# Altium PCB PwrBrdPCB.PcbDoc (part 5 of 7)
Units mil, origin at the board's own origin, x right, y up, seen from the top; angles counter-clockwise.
Board outline 8000 x 5500 mil, 4 copper layers (Top Layer, Internal 1, Internal 2, Bottom Layer), stack 61.834 mil thick; 682 components, 380 nets, 1899 pads, 766 vias.
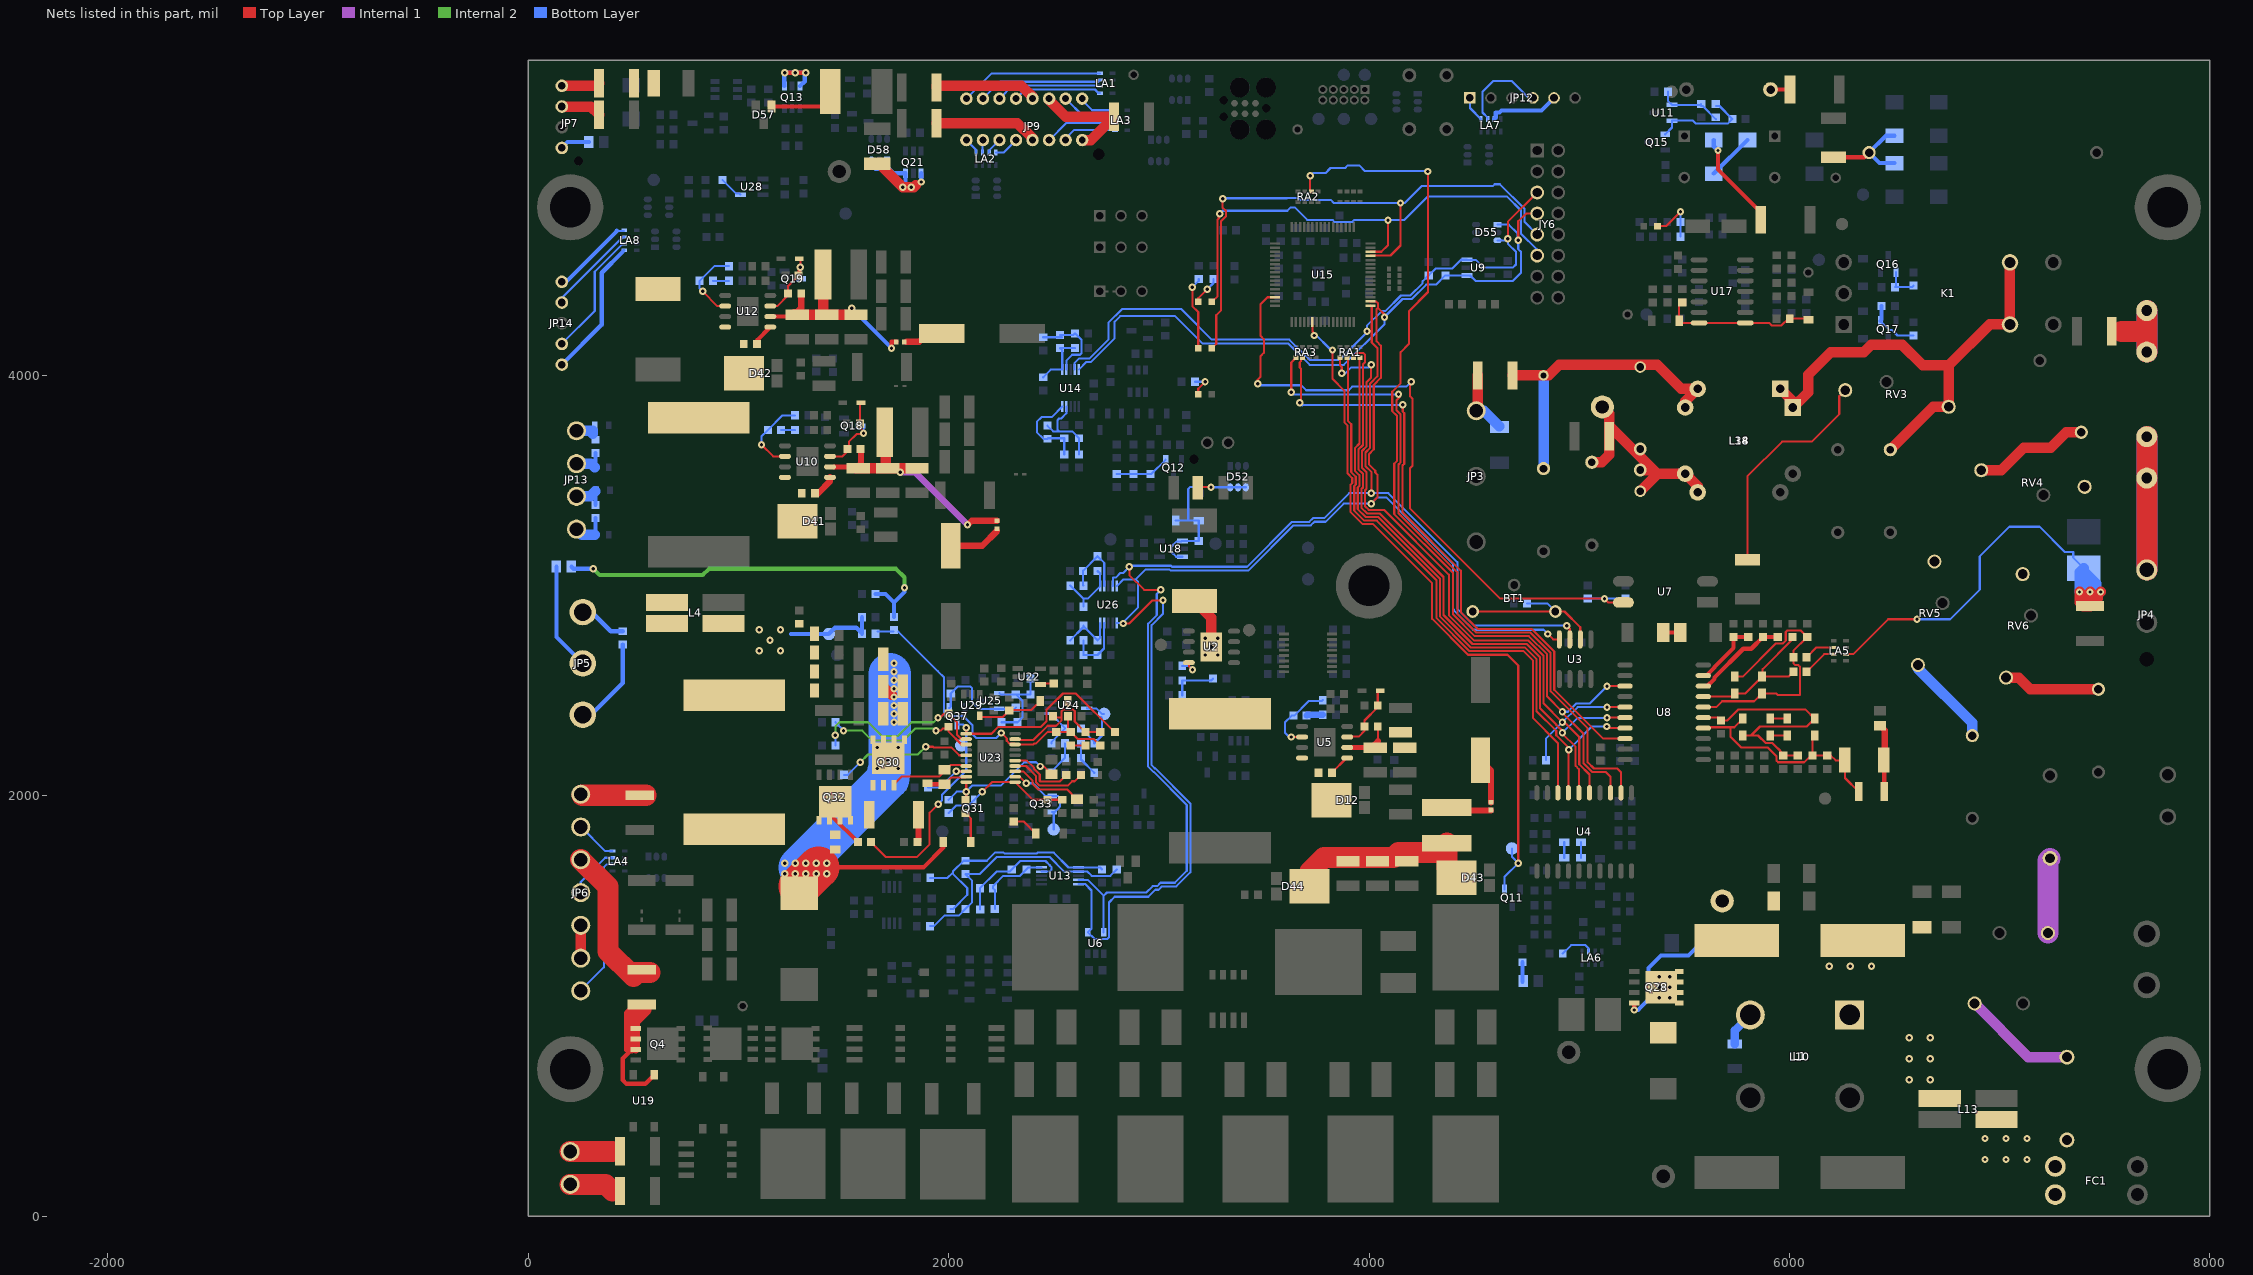
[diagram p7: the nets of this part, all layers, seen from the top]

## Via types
v1: diameter 35, hole 16, Top Layer to Bottom Layer, tented both sides, 409 vias
v2: diameter 35, hole 16, Top Layer to Bottom Layer, 348 vias
v3: diameter 35, hole 16, Top Layer to Bottom Layer, tented bottom, 5 vias
v4: diameter 60, hole 36, Top Layer to Bottom Layer, 2 vias
v5: diameter 65, hole 40.5, Top Layer to Bottom Layer, 2 vias

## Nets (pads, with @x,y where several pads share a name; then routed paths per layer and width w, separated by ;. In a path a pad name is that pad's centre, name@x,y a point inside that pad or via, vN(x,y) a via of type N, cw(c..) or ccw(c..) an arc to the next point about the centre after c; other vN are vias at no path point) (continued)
HVX_COMP: C161.2 C162.2 D54.A R148.1 U23.9 | length 648.9
  Top Layer w10: U23.9@2316.14,2269.96 2320.05,2266.05 2400.29,2266.05 2400.74,2266.5 2403.93,2266.5 2471.13,2333.69 2511.46,2333.69 2537.8,2360.04 2537.8,2373.45 ; R148.1@2497.3,2378.51 2502.36,2373.45 2537.8,2373.45 ; D54.A@2567.16,2451.25 2568.5,2449.9 2568.5,2411.68 ; C161.2@2721.5,2302.99 C162.2@2651.5,2302.99 2650.51,2302.99 2600,2353.51 2600,2402.37 2590.68,2411.68 2568.5,2411.68 ; 2537.8,2373.45 2537.8,2403.16 2546.33,2411.68 2568.5,2411.68
HVX_CS: C158.1 R171.1 U23.12 | length 877.8
  Top Layer w10: v1(1949.23,2370.77) 1959.27,2370.77 1980,2391.5 1998.5,2391.5 2040,2350 2040,2291.21 2061.25,2269.96 U23.12@2083.86,2269.96
  Internal 2 w10: v1(1461.5,2288.5) 1461.5,2331.5 1480,2350 1617.07,2350 1682.57,2284.5 1758.35,2284.5 1823.85,2350 1928.46,2350 v1(1949.23,2370.77)
  Bottom Layer w10: R171.1@1461.5,2240 v1(1461.5,2288.5)
HVX_DCBUS: C139.1 C140.1 C141.1 C142.1 C143.1 D47.A L2.2 MECH6.2 Q30.D | length 1943.1
  Top Layer w20: 1380,1660 1880,1660 1974.65,1754.65 D47.A@1974.65,1780
  Top Layer w50: C142.1@1688.07,2520 1690,2520 v2@1730,2480
  Top Layer w200: L2.2@1290,1570 1380,1660
  Bottom Layer w200: 1290,1660 1712.8,2082.8 1712.8,2111.2 1720,2118.4 1720,2130 1720,2470 1720,2580
  other v2: 1220,1630 1270,1630 1320,1630 1370,1630 1420,1630 1220,1680 1270,1680 1320,1680 1370,1680 1420,1680 1660,2130 1760,2130 1710,2170 1660,2230 1760,2230 1740,2350 1740,2390 1740,2430 1740,2470 1740,2510 1740,2550 1740,2590 1740,2630
HVX_DEMB: Q33.4 Q33.6 TP34.1 U23.2 | length 431.5
  Top Layer w10: U23.2@2316.14,2090.83 2339.17,2090.83 v1(2369.99,2059.99)
  Bottom Layer w10: v1(2369.99,2059.99) 2400.21,2059.99 2406.14,2054.09 2457,2003.23 2457,2003 2461.1,1998.9 Q33.4@2493.15,1998.9 2521.1,1998.9 2530,1990 2530,1950 2526.8,1946.8 2526.8,1944.71 2506.18,1924.09 Q33.6@2493.15,1924.09 2500,1917.24 TP34.1@2500,1840
HVX_FB: C161.1 R176.2 R178.1 R180.1 R182.1 R213.2 U23.8 | length 1546.6
  Top Layer w10: v1(2250,2299) 2251,2299 2276.58,2273.42 2276.58,2261.32 2288.8,2249.1 2311.41,2249.1 U23.8@2316.14,2244.37 2402.65,2244.37 2407.78,2249.5 2416.51,2249.5 2470,2302.99 R178.1@2511.49,2302.99 R180.1@2581.49,2302.99 ; R182.1@2568.5,2378.5 2568.5,2316.97 2582.48,2302.99 R180.1@2581.49,2302.99 ; C161.1@2721.5,2240 2690.8,2270.7 2613.79,2270.7 R180.1@2581.49,2302.99
  Bottom Layer w10: R176.2@1661.5,2781.5 R213.2@1738.5,2781.5 ; 1760.86,2780.86 1948.72,2593 1978.1,2563.62 1978.1,2388.91 1985.13,2381.88 2018.12,2381.88 2020,2380 2069.43,2380 2113.93,2335.51 2113.93,2292.7 2131.21,2275.42 2226.42,2275.42 v1(2250,2299)
HVX_HB: C147.1 D48.K U23.19 | length 187.9
  Top Layer w10: C147.1@1980,2055.55 2011.37,2086.92 U23.19@2079.95,2086.92
  Top Layer w20: D48.K@1905.04,2055.55 C147.1@1980,2055.55
HVX_HO: R163.1 U23.18 | length 214
  Top Layer w10: v1(2036.42,2116.42) U23.18@2083.86,2116.42
  Bottom Layer w10: R163.1@1901.5,2040 1960,2040 v1(2036.42,2116.42)
HVX_LO: R165.1 U23.15 | length 665.4
  Top Layer w10: v1(1890.79,2233.8) 1926.2,2233.8 1930.79,2229.21 2014.22,2229.21 2050.23,2193.19 U23.15@2083.86,2193.19
  Internal 2 w10: v1(1580,2160) 1616.5,2196.5 1673.88,2196.5 1686.88,2209.5 1733.12,2209.5 1746.12,2196.5 1853.5,2196.5 v1(1890.79,2233.8)
  Bottom Layer w10: R165.1@1501.5,2100 1520,2100 v1(1580,2160)
HVX_RAMP: C160.1 Q37.3 R170.2 TP37.1 U23.11 | length 1931.9
  Top Layer w10: R170.2@1630.75,1779.25 1700,1710 1850,1710 1910,1770 1910,1920 v1(1950,1960) ; v1(2083.86,2323.86) 2083.86,2320 U23.11@2083.86,2295.55 2204.06,2295.55 2237,2328.5 2439.66,2328.5 2465.8,2354.64 2465.8,2408.87 2544.19,2487.25 2605.34,2487.25 C160.1@2790.54,2302.04
  Bottom Layer w10: v1(1950,1960) 1968.32,1978.32 1968.32,2005.17 2083.86,2120.71 v1(2083.86,2323.86) 2068.21,2339.5 Q37.3@2040,2339.5
HVX_RES: C156.1 U23.3 | length 357.9
  Top Layer w10: U23.3@2316.14,2116.42 2355.3,2116.42 2399.49,2072.23 2399.49,2056.28 2425.77,2030 2564.45,2030 C156.1@2610,1984.45
HVX_RT: R168.1 U23.5 | length 319.7
  Top Layer w10: U23.5@2316.14,2167.6 2372.4,2167.6 2407.06,2132.94 2407.06,2127.78 2433.49,2101.36 2433.49,2070.37 2436.09,2067.76 2527.76,2067.76 R168.1@2560,2100
HVX_SS: C157.1 U23.4 | length 390.4
  Top Layer w10: U23.4@2316.14,2142.01 2367.99,2142.01 2416.49,2093.51 2416.49,2063.33 2429.81,2050 2568.28,2050 2587.78,2069.5 2599.5,2069.5 C157.1@2630,2100
HVX_SW: C147.2 L3.1 MECH6.1 Q30.S Q32.D R169.1 R170.1 U23.17 | length 547.1
  Top Layer w10: Q30.S@1740,2055.47 1775.94,2091.42 1955.47,2091.42 2009.97,2145.92 U23.17@2079.95,2145.92
  Top Layer w20: Q32.D@1448.5,1900 R170.1@1568.5,1780
HVX_UVLO: C155.1 Q31.3 R164.2 R167.1 U23.1 | length 635.5
  Top Layer w10: v1(2160,2019) 2206.24,2065.24 U23.1@2316.14,2065.24 2399.88,1981.5 R167.1@2470,1981.5 C155.1@2540,1981.5
  Bottom Layer w10: R164.2@2000,1918.5 2035.12,1953.62 2094.62,1953.62 Q31.3@2120,1979 v1(2160,2019)
HVX_VIN: C154.1 R162.2 R164.1 U23.20 | length 673.1
  Top Layer w10: R162.2@2080,1981.5 2083.86,1985.35 v1(2083.86,2020) U23.20@2083.86,2065.24 ; v1(2436.56,2140) 2452.6,2140 C154.1@2490,2102.6
  Bottom Layer w10: R164.1@2000,1981.5 2038.5,2020 v1(2083.86,2020) 2113.86,2050 2250,2050 2360,2160 2416.56,2160 v1(2436.56,2140)
HVX_VOUT: C148.1 C149.1 C150.1 C151.1 C152.1 L3.2 L4.4 R176.1 R200.1 TP36.1 | length 441.8
  Bottom Layer w20: 1250,2770 TP36.1@1430,2770 1460,2800 1560.98,2800 1588.5,2772.48 R176.1@1588.5,2771.5 R200.1@1588.5,2850
  other v2: 1100,2690 1200,2690 1150,2740 1100,2790 1200,2790
I2C.SCL: D55.1 JY6.7 R5.1 U3.8 U6.4 U9.1 U13.10 U14.10 U15.18 U26.1 U26.10 | length 9799.5
  Top Layer w10: v1(2830,2820) 2860,2820 2970,2930 v1(3020,2930) ; U15.18@4006.38,4352.05 4007.28,4351.14 4034.1,4351.14 4042,4343.24 4042,4321.49 ; v1(4010,3390) 4039.5,3419.5 4039.5,3528.28 4029.5,3538.28 4029.5,3546.47 4000.5,3575.47 4000.5,3626.26 4022.5,3648.26 4022.5,3954.43 4056.5,3988.43 4056.5,4141.85 4036.14,4162.21 4036.14,4315.63 4042,4321.49 ; v1(4073.49,4276.51) 4073.49,4290 4042,4321.49 ; v1(4710,4642.6) 4710,4733.56 4746.44,4770 JY6.7@4800,4770 ; v1(4850.51,2770) 4876.02,2744.49 U3.8@4905,2744.49
  Bottom Layer w10: U13.10@2617.6,1580.63 2649.37,1580.63 2680,1550 2680,1368.5 U6.4@2662.5,1351 2694,1319.5 2755.97,1319.5 2763,1326.53 2763,1493 2790,1520 2950,1520 2983.5,1553.5 2999.26,1553.5 3015.26,1569.5 3083.34,1569.5 3150,1636.16 3150,1963.8 2982.68,2131.12 2980.8,2131.12 2966,2145.92 2966,2811.75 3020,2865.75 v1(3020,2930) ; U14.10@2619.37,4027.6 2656.09,4064.32 2678.08,4064.32 2790,4176.23 2790,4255.96 2816.35,4282.31 3077.69,4282.31 3209,4151 3616.68,4151 3717.68,4050 3880,4050 4073.49,4243.49 v1(4073.49,4276.51) 4073.49,4277.73 4159.26,4363.5 4203.3,4363.5 4271.68,4431.87 4318.57,4431.87 4362.88,4476.18 R5.1@4363.86,4476.18 4364.31,4475.73 U9.1@4466.29,4475.73 4480.48,4475.73 4506.2,4450 4684.94,4450 4723,4488.06 4723,4587.7 4710,4600.7 v1(4710,4642.6) 4706,4646.6 4706,4676.65 4665.24,4717.4 D55.1@4610.98,4717.4 ; U26.1@2799.37,2822.4 v1@2832.4,2822.4 ; U26.10@2799.37,2997.6 2831.77,3030 2890,3030 ; v1(2830,2820) v1@2832.4,2822.4 ; v1(4850.51,2770) 4830.51,2790 4495.96,2790 4403,2882.96 4403,2887 4400,2890 4400,3101.72 4081.72,3420 4040,3420 v1(4010,3390) 3879.29,3390 3793.29,3304 3740.56,3304 3723.06,3286.5 3640.54,3286.5 3427.04,3073 3054.89,3073 3050.39,3077.5 2937.5,3077.5 2890,3030 ; v1@2832.4,2822.4 2832.4,2828.57 2901.69,2897.85 2901.69,2922.17 2901.69,3018.31 2890,3030
I2C.SDA: D55.3 JY6.5 R6.1 U3.7 U6.5 U9.3 U13.9 U14.9 U15.17 U26.9 | length 9308.3
  Top Layer w10: v1(2860,3090) 2860,3050 2930,2980 v1(3010,2980) ; v1(3990,4210) 4013,4210 ; U15.17@4006.38,4332.36 4013,4325.74 4013,4210 ; v1(4010,3440) 4010,3453.11 4012.5,3455.61 4012.5,3539.43 3983.5,3568.43 3983.5,3633.3 4005.5,3655.3 4005.5,3961.47 4039.5,3995.47 4039.5,4130.5 4013,4157 4013,4210 ; v1(4660.28,4650) 4660.28,4730.28 JY6.5@4800,4870 ; v1(4940,2810) 4955,2795 U3.7@4955,2744.49
  Bottom Layer w10: U14.9@2599.69,4027.6 2599.69,4059.69 2621.32,4081.32 2671.04,4081.32 2760,4170.27 2760,4250 2826,4316 3105.92,4316 3251.42,4170.5 3621.22,4170.5 3717.72,4074 3859.76,4074 3990,4204.24 v1(3990,4210) 3990,4235.96 4060.06,4306.01 4077.73,4306.01 4152.22,4380.5 4196.26,4380.5 4255.03,4439.27 4255.03,4448.34 4282.88,4476.18 R6.1@4283.86,4476.18 4284.84,4476.18 4317.17,4508.5 4339.17,4508.5 ; U13.9@2617.6,1600.31 2661.34,1600.31 2737.5,1524.15 ; U6.5@2737.5,1351 2737.5,1524.15 ; U26.9@2779.69,2997.6 2781.46,2999.38 2781.46,3038.32 2795.17,3038.32 2816.85,3060 2830,3060 v1(2860,3090) 2864.5,3094.5 3057.43,3094.5 3061.93,3090 3420,3090 3633.5,3303.5 3716.02,3303.5 3733.52,3321 3786.25,3321 3905.25,3440 v1(4010,3440) 4091.72,3440 4420,3111.72 4420,2890 4500,2810 v1(4940,2810) ; v1(3010,2980) 2990,2960 2990,2859.79 2949,2818.79 2949,2138.88 2973.76,2114.12 2975.64,2114.12 3133,1956.75 3133,1643.2 3076.3,1586.5 3008.22,1586.5 2992.22,1570.5 2970.5,1570.5 2940,1540 2753.35,1540 2737.5,1524.15 ; 4339.2,4508.47 4395.62,4508.47 4437.68,4550.53 U9.3@4466.29,4550.53 4466.98,4549.84 4507.29,4549.84 4544,4513.13 4684.14,4513.13 4698.84,4527.82 4698.84,4587.82 4660.28,4626.38 4660.28,4638.19 4655.87,4642.6 D55.3@4610.98,4642.6
input_ok: C38.1 D19.A D22.A R55.1 U17.7 U17.8 | length 747.5
  Top Layer w10: R55.1@5475.35,4353.86 R55.1@5475.35,4347.01 ; R55.1@5490,4347.01 R55.1@5475.35,4347.01 ; D22.A@6090,4264.65 6084.64,4270 C38.1@6001.5,4270 5993.86,4270 5962.17,4238.32 5914.83,4238.32 5903.15,4250 U17.8@5790,4250 U17.7@5570,4250 5485.35,4250 D19.A@5475.35,4260 R55.1@5475.35,4347.01
L1: FC3.1 JP4.2 | length 1266.9
  Top Layer w100: JP4.2@7700,3075 FC3.1@7700,3511.57 FC3.1@7700,3708.43
  Bottom Layer w100: JP4.2@7700,3075 FC3.1@7700,3511.57 FC3.1@7700,3708.43
L2: C39.1 CX2.1 L17.1 L18.2 L34.2 TP3.1 | length 1504.6
  Top Layer w50: L17.1@4682.87,4000 TP3.1@4830,4000 4854.15,4000 4904.47,4050.32 5370.39,4050.32 5484.65,3936.06 L18.2@5563.15,3936.06 5504.09,3877.01 L34.2@5504.09,3847.48
  Bottom Layer w50: C39.1@4830,3556.85 TP3.1@4830,4000
LED0: D3.K JY6.9 U15.29 | length 2796
  Top Layer w10: D3.K@3252.48,4130 3273,4150.52 3273,4286.76 3296.5,4310.26 3296.5,4734.78 3319.5,4757.78 3319.5,4782.22 3303.77,4797.94 v1(3303.77,4840) ; U15.29@4006.38,4568.58 4008.16,4570.36 4102.08,4570.36 4150,4618.28 v1(4150,4820)
  Bottom Layer w10: v1(3303.77,4840) 3300.77,4843 3609.06,4843 3609.56,4843.5 3664.57,4843.5 3672.57,4835.5 3817.11,4835.5 3832.61,4820 v1(4150,4820) 4170,4820 4252,4902 4590.28,4902 4597.78,4909.5 4622.22,4909.5 4740,4791.72 4740,4730 JY6.9@4800,4670
LED1: D1.K JY6.11 U15.30 | length 2449.5
  Top Layer w10: D1.K@3252.48,4350 3279.5,4377.02 3279.5,4741.82 3285.22,4747.54 3285.22,4765.22 v1(3290,4770) ; U15.30@4006.38,4588.27 4058.27,4588.27 4090,4620 v1(4090,4739)
  Bottom Layer w10: v1(3290,4770) 3303.5,4783.5 3611.78,4783.5 3627.78,4799.5 3646.35,4799.5 3705.85,4740 3826.14,4740 3835.34,4730.8 3920.8,4730.8 3929.5,4739.5 4168.22,4739.5 4280.49,4851.77 4596.51,4851.77 4597.78,4850.5 4657.18,4850.5 4723,4784.68 4723,4674.81 4800,4597.81 JY6.11@4800,4570
Lfiltered: C40.2 JP3.5 L17.2 | length 311.7
  Top Layer w50: JP3.5@4510,3832 4517.13,3839.13 L17.2@4517.13,4000
  Bottom Layer w50: JP3.5@4510,3832 4545.88,3832 C40.2@4620,3757.88
LPROT: C30.1 K1.COM L18.1 L34.1 RV3.1 | length 2293.1
  Top Layer w50: L18.1@5956.85,3936.06 6015.91,3877.01 L34.1@6015.91,3847.48 6089.05,3920.62 6089.05,4002.78 6196.27,4110 6353.75,4110 6389.27,4145.52 6535.46,4145.52 6633.34,4047.64 6757.64,4047.64 ; C30.1@6480,3646.85 6684.09,3850.94 RV3.1@6757.64,3850.94 6757.64,4047.64 ; K1.COM@7049.05,4537.64 K1.COM@7049.05,4242.36 6952.36,4242.36 6757.64,4047.64
MON.ADC_CLK: RA2.2 U4.13 U8.13 | length 4673.4
  Top Layer w10: v1(3720,4950) 3720,4881.34 RA2.2@3725.75,4875.59 ; v1(4280,4970) 4280.5,4969.5 4280.5,4396.66 4190,4306.16 4190,4150 4150.25,4110.25 4150.25,3961.97 4110.5,3922.22 4110.5,3830.04 4133.5,3807.04 4133.5,3593.7 4120,3580.2 4120,3340 4400,3060 4400,2862.68 4502.68,2760 4760,2760 4847.19,2672.81 4847.19,2472.81 v1(4920,2400) 4920,2395.96 5020,2295.96 5020,2155.96 5062.96,2113 5127,2113 5148.5,2091.5 U4.13@5148.5,2014.65 ; v1(5132.24,2522.24) U8.13@5218.07,2522.24
  Bottom Layer w10: v1(3720,4950) 3732.5,4962.5 3792.86,4962.5 3816.86,4986.5 3886.7,4986.5 3899.45,4999.25 3952.87,4999.25 3979.61,4972.5 3997.3,4972.5 3997.61,4972.19 4277.81,4972.19 v1(4280,4970) ; v1(4920,2400) 4945.96,2400 4985.2,2439.24 5049.24,2439.24 v1(5132.24,2522.24)
MON.C\S\_MAINS: RA3.6 U8.18 | length 2977.4
  Top Layer w10: v1(3670,3870) 3676.57,3876.57 3676.57,4031.71 3670.5,4037.78 3670.5,4062.22 3676.57,4068.29 3676.57,4076.72 RA3.6@3684.25,4084.41 ; v1(4160,3860) 4165,3860 4170,3855 4160.5,3845.5 4160.5,3828.12 4167.5,3821.12 4167.5,3579.61 4159.5,3571.61 4159.5,3348.58 4437,3071.08 4437,2873.76 4516.76,2794 4774.08,2794 4881.19,2686.89 4881.19,2504.57 5113.52,2272.24 U8.18@5218.07,2272.24
  Bottom Layer w10: v1(3670,3870) 3683,3857 3686,3860 v1(4160,3860)
MON.C\S\_PV: RA1.6 U4.18 | length 2678.2
  Top Layer w10: RA1.6@3894.25,4084.41 3899.5,4079.16 3899.5,3784.53 3915.5,3768.53 3915.5,3540.26 3937,3518.76 3937,3481.24 3929.5,3473.74 3929.5,3356.66 3976.66,3309.5 4037.36,3309.5 4320,3026.86 4320,2890.95 4320,2846.51 4478.1,2688.41 4735.42,2688.41 4779.19,2644.64 4779.19,2370.81 4898.5,2251.5 U4.18@4898.5,2014.65
MON.CAL: Q11.1 TP18.1 U15.6 | length 3384
  Top Layer w10: U15.6@3730.79,4253.62 3730.79,4209.21 3740,4200 v1(3740,4190) ; v1(3826.45,4120.88) 3826.45,3983.55 3882.5,3927.5 3882.5,3777.49 3898.5,3761.49 3898.5,3533.22 3920,3511.72 3920,3488.28 3912.5,3480.78 3912.5,3349.61 3969.61,3292.5 4019.61,3292.5 4300,3012.11 4300,2842.47 4471.06,2671.41 4658.59,2671.41 4710,2620 v1(4710,1680)
  Bottom Layer w10: v1(3740,4190) 3740,4200 3819.12,4120.88 v1(3826.45,4120.88) ; Q11.1@4644.02,1554.65 4644.02,1614.02 v1(4710,1680) 4680,1710 TP18.1@4680,1750
MON.D\R\_PV: RA3.5 U4.12 | length 3263.4
  Top Layer w10: v1(3630,3920) 3630,4061.65 RA3.5@3652.76,4084.41 ; v1(4140,3910) 4147,3910 4147,3898.72 4130.5,3882.22 4130.5,3834.08 4150.5,3814.08 4150.5,3586.66 4140,3576.16 4140,3344.04 4420,3064.04 4420,2866.72 4509.72,2777 4767.04,2777 4864.19,2679.85 4864.19,2497.53 5040,2321.72 5040,2160 5070,2130 5180,2130 5198.5,2111.5 U4.12@5198.5,2014.65
  Bottom Layer w10: v1(3630,3920) 3640,3910 v1(4140,3910)
MON.MISO: R17.2 RA1.5 U4.15 U8.15 | length 3481.9
  Top Layer w10: RA1.5@3862.76,4084.41 3862.76,4047.24 3870,4040 v1(3870,4010) ; v1(4010,4050) 4010,3990.01 3988.5,3968.51 3988.5,3662.34 3966.5,3640.34 3966.5,3561.39 3988,3539.89 3988,3460.11 3980.5,3452.61 3980.5,3377.78 3997.78,3360.5 4071.22,3360.5 4380,3051.72 4380,2858.64 4498.64,2740 4755.96,2740 4830.19,2665.77 4830.19,2439.81 v1(4920,2350) 4930,2350 5000,2280 5000,2150 5048.5,2101.5 U4.15@5048.5,2014.65 ; v1(5132.24,2422.24) U8.15@5218.07,2422.24
  Bottom Layer w10: v1(3870,4010) 3887.68,4010 3916.17,4038.49 3998.49,4038.49 v1(4010,4050) ; R17.2@4841.5,2170 4841.5,2271.5 v1(4920,2350) 4992.24,2422.24 v1(5132.24,2422.24)
MON.MOSI: RA1.7 U4.16 U8.16 | length 3125.1
  Top Layer w10: RA1.7@3925.75,4084.41 3925.75,4091.54 3940.46,4106.25 3974.03,4106.25 3981.06,4099.22 3981.06,4062.77 3971.5,4053.22 3971.5,3669.39 3949.5,3647.39 3949.5,3554.34 3971,3532.84 3971,3467.16 3963.5,3459.66 3963.5,3370.74 3990.74,3343.5 4051.45,3343.5 4354,3040.95 4354,2860.59 4492.19,2722.41 4749.51,2722.41 4813.19,2658.73 4813.19,2416.81 4890.5,2339.5 4890.5,2337.78 4907.78,2320.5 4909.5,2320.5 4920,2310 v1(4920,2300) 4920,2295.96 4983,2232.96 4983,2142.96 4998.5,2127.45 U4.16@4998.5,2014.65 ; v1(5132.24,2372.24) U8.16@5218.07,2372.24
  Bottom Layer w10: v1(4920,2300) 4990,2370 5130,2370 v1(5132.24,2372.24)
MON.MOV_BAD: C43.1 R81.2 U7.4 U15.62 | length 3234.2
  Top Layer w10: v1(3470,3960) 3470,3980.2 3483.5,3993.7 3483.5,4091.78 3499.5,4107.78 3499.5,4172.22 3483.5,4188.22 3483.5,4338.21 3517.02,4371.73 U15.62@3553.62,4371.73 ; v1(4200,3970) 4195.57,3965.57 4195.57,3900.19 4206.5,3889.26 4206.5,3570.53 4195.57,3559.6 4195.57,3366.51 4623.58,2938.5 v1(5120,2938.5) 5138.5,2920 U7.4@5210,2920
  Bottom Layer w10: v1(3470,3960) 3476.5,3953.5 3676.7,3953.5 3700.7,3929.5 3903.34,3929.5 3920.34,3946.5 4176.5,3946.5 v1(4200,3970) ; R81.2@5040,2938.5 v1(5120,2938.5) C43.1@5220,2938.5
MON.SCLK: RA1.8 U4.17 U8.17 | length 3011.5
  Top Layer w10: RA1.8@3957.24,4084.41 3954.5,4081.67 3954.5,3676.43 3932.5,3654.43 3932.5,3547.3 3954,3525.8 3954,3474.2 3946.5,3466.7 3946.5,3363.7 3983.7,3326.5 4044.4,3326.5 4337,3033.9 4337,2853.55 4485.14,2705.41 4742.47,2705.41 4796.19,2651.69 4796.19,2403.81 4890.5,2309.5 4890.5,2287.78 4950,2228.28 v1(4950,2220) 4948.5,2218.5 U4.17@4948.5,2014.65 ; v1(5130,2330) 5137.76,2322.24 U8.17@5218.07,2322.24
  Bottom Layer w10: v1(4950,2220) 5060,2330 v1(5130,2330)
MON_IA+: C86.1 D36.A D37.K R104.2 U8.7 | length 727.3
  Top Layer w10: U8.7@5590.12,2472.24 5723.74,2472.24 D36.A@5738.74,2487.24 5789.45,2487.24 D37.K@5869.45,2567.24 ; D37.K@5873.39,2568.81 D37.K@5872.2,2570 ; C86.1@6014.1,2755.75 6014.1,2744.1 5872.2,2602.2 D37.K@5872.2,2570 ; R104.2@6018.5,2590 5995.75,2567.24 D37.K@5869.45,2567.24 ; D37.K@5869.45,2567.24 D37.K@5872.2,2570
MON_IA-: C79.2 D36.K D37.A R103.1 U8.6 | length 1286.7
  Top Layer w10: U8.6@5590.12,2422.24 5652.24,2422.24 5680,2450 5832.2,2450 D36.K@5869.45,2487.24 5937.24,2487.24 5944.49,2480 6050,2480 6050,2613.86 6042.18,2621.69 6028.31,2621.69 6018.35,2631.65 6018.35,2690 C79.2@6084.09,2755.75 6053.39,2786.45 5989.44,2786.45 5982.41,2779.42 5982.41,2738.71 5968.75,2725.05 5935.05,2725.05 5777.24,2567.24 D37.A@5738.74,2567.24
MON_LDO: C80.1 C81.1 U8.8 | length 454.7
  Top Layer w20: U8.8@5590.12,2522.24 5609,2522.24 5643.54,2556.78 5643.54,2563.54 5780,2700 5818.35,2700 C81.1@5874.1,2755.75 C80.1@5944.1,2755.75
MON_REF: C82.1 C83.1 U8.9 | length 322.1
  Top Layer w20: U8.9@5590.12,2572.24 5605.47,2572.24 5643.54,2610.31 5643.54,2613.54 5734.1,2704.1 C82.1@5734.1,2755.75 C83.1@5804.1,2755.75
MON_V+: C77.1 D27.K D33.A R99.2 R100.2 R215.2 U8.4 | length 1137.9
  Top Layer w10: U8.4@5590.12,2322.24 5590.12,2326.45 5720,2326.45 ; D33.A@5778.74,2367.24 5737.94,2326.45 5720,2326.45 ; D27.K@6119.45,2287.24 6110,2277.8 C77.1@6110,2191.5 ; R99.2@6240.76,2168.62 6220.14,2168.62 6197.27,2191.5 R100.2@6180,2191.5 6150,2191.5 C77.1@6110,2191.5 ; R99.2@6263.94,2170 6263.94,2085.04 R215.2@6328.98,2020 ; 5720,2326.45 5720,2280 5770,2230 5896.85,2230 5938.31,2188.54 5938.31,2167.82 5946.14,2160 6070,2160 6101.5,2191.5 C77.1@6110,2191.5
MON_V-: C78.1 D34.A D35.K R101.2 R102.2 U8.5 | length 1201.8
  Top Layer w10: U8.5@5590.12,2372.24 5660.59,2372.24 R102.2@5674.09,2358.74 5704.24,2358.74 5755.5,2410 6076.69,2410 D35.K@6119.45,2367.24 6082.2,2330 5860,2330 5817.24,2287.24 ; D34.A@5778.74,2287.24 5817.24,2287.24 ; 5959.55,2210.45 5955.31,2214.69 5955.31,2215.58 5945.36,2225.54 5944.46,2225.54 5918.76,2251.24 5886.48,2251.24 5850.48,2287.24 5817.24,2287.24 ; C78.1@5970,2200.9 C78.1@5970,2191.5 R101.2@6040,2191.5
MOV1: RV4.3
MOV2: RV5.3
MOV3: RV6.3
MOV4: R85.2 RV3.3 | length 1078.7
  Top Layer w10: R85.2@5800,3126.46 5800,3520 5965.11,3685.11 6106.22,3685.11 6237.05,3815.93 6237.05,3901.22 RV3.3@6265.51,3929.69
N1: L20.2 LA5.2 R77.1 | length 2210.2
  Top Layer w10: LA5.2@6269.53,2674.25 6304.25,2674.25 6470,2840 v1(6606.83,2840)
  Top Layer w50: v2(7380,2970) 7380,2920 7397.13,2902.87 L20.2@7430,2902.87 ; v1(7430,2970) L20.2@7430,2902.87 ; v2(7480,2970) 7467.09,2957.09 7467.09,2939.96 L20.2@7430,2902.87
  Bottom Layer w10: v1(6606.83,2840) 6764.04,2840 6905.22,2981.18 6905.22,3139.18 7046.04,3280 7190,3280 7310,3160 7350,3160 7350,3133.39 R77.1@7400,3083.39
  Bottom Layer w50: v2(7380,2970) 7380,3063.39 R77.1@7400,3083.39 R77.1@7400,3069 ; v1(7430,2970) 7400,3000 R77.1@7400,3069 ; v2@7467.09,2967.09 7459,2975.17 7459,3010 R77.1@7400,3069
N2: C42.2 CX2.2 L18.3 L19.1 L34.3 TP21.1 | length 1086.5
  Top Layer w50: C42.2@5060,3586.85 5106.85,3586.85 5142.87,3622.87 L19.1@5142.87,3710 L19.1@5142.87,3760 ; TP21.1@5110,3850 5142.87,3817.13 L19.1@5142.87,3760 ; CX2.2@5290,3449.45 5373.07,3532.52 ; v4(5290,3550) 5350,3550 5351.44,3551.44 ; L18.3@5563.15,3443.94 5563.15,3473.46 L34.3@5504.09,3532.52 5373.07,3532.52 ; L19.1@5142.87,3760 5321.44,3581.44 5351.44,3551.44 ; 5351.44,3551.44 5370.35,3532.52 5373.07,3532.52
  other v4: 5290,3650
NEG1: C71.2 L1.1 L10.1 L13.2
  other v2: 6570,650 6670,650 6570,750 6670,750 6570,850 6670,850 6190,1190 6290,1190 6390,1190
NEG2: C2.2 CX1.2 D8.1 L1.2 L10.2 Q28.D TP11.1 | length 169.3
  Bottom Layer w40: CX1.2@5740,819.25 5740,884.25 L1.2@5813.78,958.03
  other v1: 5380,1040 5430,1040 5380,1090 5430,1090 5380,1140 5430,1140
NetBT1_+: BT1.+ C182.1 U3.6 | length 751.7
  Top Layer w10: BT1.+@4493.15,2877.01 BT1.+@4886.85,2877.01 4930,2877.01 5005,2802.01 U3.6@5005,2744.49
  Bottom Layer w10: C182.1@4751.5,2915.42 4848.43,2915.42 BT1.+@4886.85,2877.01
NetC14_1: C14.1 Q12.1 R37.1 R38.1 | length 260.6
  Bottom Layer w10: R37.1@2800,3531.5 R38.1@2880,3531.5 C14.1@2960,3531.5 2965.1,3531.5 Q12.1@3032.6,3599
NetC17_1: C17.1 U5.1 | length 99
  Top Layer w10: C17.1@3822.99,2110 U5.1@3892.99,2180
NetC17_2: C17.2 D12.K L6.1 U5.8
NetC24_1: C24.1 C131.1 C132.1 L46.2 R41.1 R138.1 U5.2 | length 446
  Top Layer w10: 4042.99,2259.56 R41.1@4042.99,2330
  Top Layer w23: U5.2@3896.06,2230 C131.1@4009.57,2230
  Top Layer w30: C131.1@4009.57,2230 4011.5,2228.07 4042.99,2259.56 ; L46.2@4370,1944.65 L46.2@4381.65,1932.99 ; L46.2@4381.65,1930 R138.1@4580,1930
NetC26_1: C26.1 R44.2 | length 78.5
  Bottom Layer w30: R44.2@3702.99,2381.93 3706.54,2385.47 C26.1@3780,2385.47
NetC27_1: C27.1 R44.1 U5.6 | length 363.5
  Top Layer w10: v1(3630,2280) U5.6@3681.5,2280
  Bottom Layer w10: v1(3630,2280) 3620,2280 3600,2300 3600,2350 3631.93,2381.93 R44.1@3640,2381.93 3643.65,2381.93 3712.22,2450.5 3775.03,2450.5 C27.1@3780,2455.47
NetC28_1: C28.1 U2.4 | length 96.8
  Top Layer w10: U2.4@3142.72,2633.5 3142.72,2617.28 v1(3160,2600)
  Bottom Layer w10: C28.1@3111.5,2618.5 3141.5,2618.5 v1(3160,2600)
NetC31_2: C31.2 D14.K D38.A R91.2 | length 474.5
  Top Layer w20: R91.2@6210,5037.48 6356.14,5037.48 C31.2@6378.66,5060
  Bottom Layer w20: D14.K@6500,5010 6428.66,5010 C31.2@6378.66,5060 6458.66,5140 D38.A@6500,5140
NetC36_1: C36.1 Q16.1 R61.2 | length 164.9
  Bottom Layer w10: Q16.1@6507.4,4491 6507.4,4425.9 R61.2@6501.5,4420 6582.99,4420 C36.1@6590,4427.01
NetC37_1: C37.1 Q17.1 R68.2 | length 259.4
  Bottom Layer w10: Q17.1@6432.6,4259 6474.98,4216.62 6487.47,4216.62 6514.09,4190 C37.1@6590,4190
  Bottom Layer w20: Q17.1@6432.6,4259 6438.5,4264.9 R68.2@6438.5,4330
NetC49_1: C49.1 C177.1 R89.1 | length 221.2
  Bottom Layer w10: C177.1@3111.5,2478.5 C49.1@3111.5,2548.5 3248.5,2548.5 R89.1@3258.51,2558.5
NetC62_1: C62.1 Q15.1 R97.1 U11.2 | length 485.1
  Bottom Layer w10: Q15.1@5409,5147.4 5441.34,5179.74 U11.2@5441.34,5212.6 5540.55,5212.6 5555.34,5197.8 5706.31,5197.8 R97.1@5728.5,5220 5667.01,5281.5 C62.1@5650,5281.5
NetC62_2: C62.2 R106.2 R107.1 U11.1 | length 307.3
  Bottom Layer w10: R106.2@5421.5,5350 5421.5,5307.24 U11.1@5441.34,5287.4 5575.91,5287.4 R107.1@5580,5291.5 ; R107.1@5580,5281.5 5587.01,5281.5 C62.2@5650,5218.5
NetC64_1: C64.1 C181.1 D2.K D9.K D52.4 D52.5 D52.6 U18.1 U18.3 | length 925.4
  Top Layer w10: C181.1@3186.14,3465.52 3189.13,3468.5 v1(3247.9,3468.5)
  Bottom Layer w10: D2.K@3080,3309.29 3135,3309.29 ; U18.1@3108.58,3211.54 3107.98,3210.95 3084.8,3210.95 3060,3186.14 3060,3160 3082.41,3137.59 U18.3@3111.64,3137.59 ; U18.1@3112.23,3212.99 C64.1@3190,3212.99 D9.K@3190,3309.29 3135,3309.29 ; D52.4@3414.24,3467.66 3413.82,3468.08 3248.32,3468.08 v1(3247.9,3468.5) 3246.41,3470 3150,3470 3140,3460 3140,3314.29 3135,3309.29
NetC84_2: C84.2 C85.1 | length 81.5
  Top Layer w20: C85.1@5398.74,2777.24 C84.2@5480.24,2777.24
NetC90_1: C90.1 U10.1 | length 113.7
  Top Layer w30: C90.1@1364.49,3440 1380,3440 1435.91,3495.91 U10.1@1435.91,3515
NetC90_2: C90.2 D41.K L39.1 U10.8
NetC93_1: C93.1 JP13.1 L40.2 | length 177.2
  Bottom Layer w20: L40.2@316.54,3242.87 320,3246.34 C93.1@320,3321.38
  Bottom Layer w50: JP13.1@230,3268.87 256,3242.87 L40.2@316.54,3242.87
NetC93_2: C93.2 JP13.2 L41.2 | length 170.1
  Bottom Layer w20: C93.2@320,3384.37 320,3449.8 L41.2@323.07,3452.87
  Bottom Layer w50: JP13.2@230,3424.78 294.98,3424.78 L41.2@320,3449.8
NetC94_1: C94.1 C95.1 C125.1 L16.2 R111.1 R136.1 U10.2 | length 1235.3
  Top Layer w23: U10.2@1455,3565 C94.1@1554.57,3565
  Top Layer w30: C94.1@1554.57,3565 1561.5,3558.07 1582.99,3579.57 R111.1@1582.99,3650 ; v1(2090,3290) 2091.5,3290 2110,3308.5 R136.1@2230,3308.5
  Top Layer w50: C94.1@1561.5,3558.07 C125.1@1701.5,3558.07 ; L16.2@1696.85,3730 1701.5,3725.35 C125.1@1701.5,3558.07 ; C95.1@1841.5,3558.07 C125.1@1701.5,3558.07
  Internal 1 w30: v2(1770,3540) 1840,3540 v1(2090,3290)
NetC96_1: C96.1 R113.2 | length 67
  Bottom Layer w10: R113.2@1202.99,3740 C96.1@1270,3740
NetC97_1: C97.1 R113.1 U10.6 | length 375.5
  Top Layer w10: v1(1110,3670) 1165,3615 U10.6@1221.34,3615
  Bottom Layer w10: v1(1110,3670) 1110,3710 R113.1@1140,3740 1210,3810 C97.1@1270,3810
NetC98_1: C98.1 U12.1 | length 106.1
  Top Layer w20: C98.1@1088.62,4150 1088.62,4166.93 U12.1@1151.69,4230
NetC98_2: C98.2 D42.K L42.1 U12.8
NetC101_1: C101.1 JP13.3 L43.2 | length 163.9
  Bottom Layer w20: L43.2@316.54,3562.87 320,3566.34 C101.1@320,3631.38
  Bottom Layer w50: JP13.3@230,3580.68 298.72,3580.68 L43.2@316.54,3562.87
NetC101_2: C101.2 JP13.4 L44.2 | length 89.8
  Bottom Layer w50: JP13.4@230,3736.59 306.59,3736.59 306.59,3723.41
NetC102_1: C102.1 C103.1 C128.1 L45.2 R119.1 R137.1 U12.2 | length 1003.2
  Top Layer w20: U12.2@1170,4280 C102.1@1257.13,4280 ; v1(1728,4130) 1728,4162 1730,4160 R137.1@1751.5,4160
  Top Layer w30: C102.1@1257.13,4280 1267.13,4290 1298.62,4321.5 R119.1@1298.62,4380
  Top Layer w50: C102.1@1267.13,4290 1269.06,4288.07 C102.1@1280,4288.07 C128.1@1407.13,4288.07 ; L45.2@1402.48,4480 1402.48,4292.72 C128.1@1407.13,4288.07 ; C103.1@1547.13,4288.07 C128.1@1420,4288.07 C128.1@1407.13,4288.07
  Bottom Layer w20: v2(1540,4320) 1540,4318 v1(1728,4130)
NetC104_1: C104.1 R121.2 | length 77
  Bottom Layer w10: R121.2@878.62,4450 C104.1@955.63,4450
NetC105_1: C105.1 R121.1 U12.6 | length 361.1
  Top Layer w10: v1(830,4400) 900,4330 U12.6@937.13,4330
  Bottom Layer w10: v1(830,4400) 815.63,4414.37 R121.1@815.63,4450 885.63,4520 C105.1@955.63,4520
NetC107_1: C107.1 C176.2 R131.2 R210.2 U13.7 | length 1201.2
  Bottom Layer w10: R210.2@1911.5,1380 1930,1380 1980,1430 2048.5,1430 R131.2@2080,1461.5 2111.69,1493.18 2111.69,1596.82 C176.2@2080,1628.5 2148.5,1628.5 2230,1710 2257.88,1710 2259.28,1708.6 2333.92,1708.6 2334.22,1708.3 2425.78,1708.3 2427.48,1710 2480,1710 2550.32,1639.69 U13.7@2617.6,1639.69 2617.91,1640 2660,1640 2680.7,1619.3 2769.3,1619.3 C107.1@2800,1650
NetC108_1: C108.1 C176.1 R130.2 R208.2 U13.6 | length 1148.3
  Bottom Layer w10: R208.2@1912.73,1610 1931.5,1610 1994.94,1610 2020,1635.06 ; R130.2@2010,1461.5 2021.5,1461.5 2088.73,1528.73 2088.73,1561.39 2020,1630.12 2020,1635.06 ; C108.1@2730,1650 2720.63,1659.37 U13.6@2617.6,1659.37 2570.63,1659.37 2500,1730 2423.44,1730 2418.74,1725.3 2341.26,1725.3 2340.96,1725.6 2266.32,1725.6 2261.92,1730 2220,1730 2181.5,1691.5 C176.1@2080,1691.5 2071.5,1691.5 2020,1640 2020,1635.06
NetC109_1: C109.1 C175.2 R129.2 U13.5 | length 380.8
  Bottom Layer w10: R129.2@2220,1461.5 2220,1551.5 C175.2@2211.5,1560 2211.5,1571.5 2259.3,1619.3 2339.3,1619.3 C109.1@2370,1650 2379.37,1659.37 U13.5@2442.4,1659.37
NetC110_1: C110.1 C175.1 R128.2 U13.4 | length 571
  Bottom Layer w10: R128.2@2150,1460 2150,1558.51 C175.1@2148.5,1560 2228.5,1640 2290,1640 C110.1@2300,1650 2340,1690 2461.22,1690 2480.98,1670.25 2480.98,1669.02 2490,1660 2490,1650 2479.68,1639.69 U13.4@2442.4,1639.69
NetC112_1: C112.1 C179.2 R135.2 U14.7 | length 400.5
  Bottom Layer w10: R135.2@2450,4181.5 C179.2@2539.88,4181.5 ; C179.2@2530,4192.99 2594.37,4192.99 C112.1@2601.38,4200 2632.08,4169.3 2632.08,4105.35 2625.05,4098.32 2588.32,4098.32 2560.32,4070.32 U14.7@2560.32,4027.6
NetC113_1: C113.1 C179.1 R134.2 U14.6 | length 283.8
  Bottom Layer w10: R134.2@2450,3991.5 2486.1,4027.6 U14.6@2540.63,4027.6 2540.63,4119.37 C179.1@2530,4130 C113.1@2601.38,4130
NetC114_1: C114.1 C178.2 R133.2 U14.5 | length 421.9
  Bottom Layer w10: U14.5@2540.63,3852.4 2490,3801.77 2441.77,3801.77 2420,3780 2420,3730 2451.5,3698.5 C178.2@2470,3698.5 2472.88,3701.38 C114.1@2550,3701.38 R133.2@2550,3624.37
NetC115_1: C115.1 C178.1 R132.2 U14.4 | length 396.8
  Bottom Layer w10: C178.1@2470,3761.5 2497.83,3733.67 2525.34,3733.67 ; U14.4@2560.32,3852.4 2560.32,3820.32 2535.07,3795.07 2525.07,3795.07 2518.31,3788.31 2518.31,3740.7 2525.34,3733.67 ; R132.2@2620,3624.37 C115.1@2620,3701.38 2587.71,3733.67 2525.34,3733.67
NetC116_+: C116.+ R136.2 | length 249
  Top Layer w30: C116.+@2010,3190 2160,3190 2230,3260
NetC118_+: C118.+ R137.2 | length 179.5
  Top Layer w30: 1800,4160 1860,4160 1869.33,4169.33 1874.65,4169.33 1880,4174.69 1880,4180 C118.+@1968.11,4180
NetC120_+: C120.+ R138.2 | length 219.8
  Top Layer w30: C120.+@4530,2169.06 4580,2119.06 R138.2@4580,1970
NetC121_1: C121.1 C129.1 C130.1 D43.K D44.K L46.1 | length 960.8
  Top Layer w100: D44.K@3720,1570 3720,1640 3785.91,1705.91 4116.52,1705.91 4140.6,1730 4324.65,1730 L46.1@4370,1775.35 4370,1656.69 D43.K@4416.69,1610
NetC144_1: C144.1 U22.4 | length 79.7
  Top Layer w10: U22.4@2423.15,2527.01 2430.04,2533.9 C144.1@2500,2533.9
NetC153_1: C153.1 JP5.1 L4.3 | length 394.7
  Bottom Layer w20: JP5.1@300,2387.4 450,2537.4 C153.1@450,2720
NetC153_2: C153.2 JP5.3 L4.2 | length 188.4
  Bottom Layer w20: JP5.3@300,2875.59 392.6,2782.99 C153.2@450,2782.99
NetC158_2: C158.2 R175.1 U23.13 | length 725.5
  Top Layer w10: v1(1940,2310) 1961.5,2310 1971.5,2320 C158.2@1985.62,2320 ; C158.2@2000,2328.5 2000,2305.62 2061.25,2244.37 U23.13@2083.86,2244.37
  Internal 2 w10: v1(1500,2310) 1590,2310 1637,2263 1645.62,2263 1646.12,2263.5 1773.88,2263.5 1774.38,2263 1783,2263 1840,2320 1930,2320 v1(1940,2310)
  Bottom Layer w10: R175.1@1461.5,2350 1500,2311.5 v1(1500,2310)
NetC159_1: C159.1 R169.2 | length 132.7
  Top Layer w30: C159.1@1851.5,1780 1857.12,1785.63 R169.2@1857.12,1910.39
NetC162_1: C162.1 R180.2 | length 70
  Top Layer w10: R180.2@2581.49,2240 C162.1@2651.5,2240
NetC163_1: C163.1 R184.1 R185.2 | length 166.1
  Bottom Layer w10: R185.2@2630,2250 C163.1@2630,2180 2630,2172.99 R184.1@2692.99,2110
NetC164_1: C164.1 R185.1 TP38.1 U24.3 | length 331.7
  Bottom Layer w10: C164.1@2630,2320 2692.99,2257.01 R185.1@2692.99,2250 2696.5,2253.51 2730,2287.01 2730,2370 TP38.1@2725,2375 ; U24.3@2658.11,2417.21 2659.26,2416.06 2703.08,2416.06 2729.14,2390 TP38.1@2740,2390
NetC165_1: C165.1 Q37.1 R188.1 U25.2 | length 481.4
  Bottom Layer w10: Q37.1@2002.6,2417.5 2010,2424.9 R188.1@2010,2487.01 2042.49,2519.5 2104.36,2519.5 2111.69,2512.17 2111.69,2445.08 2142.67,2414.09 U25.2@2241.34,2414.09 2314.09,2414.09 C165.1@2320,2420
NetC165_2: C165.2 C180.1 R191.2 R192.2 R195.1 U25.1 | length 460.8
  Bottom Layer w10: U25.1@2241.34,2488.9 2247.24,2482.99 C165.2@2320,2482.99 ; R195.1@2251.5,2350 R191.2@2328.5,2350 2351.68,2373.18 2351.68,2451.31 C165.2@2320,2482.99 ; C180.1@2390,2560 R192.2@2390,2482.99 C165.2@2320,2482.99
NetC166_1: C166.1 R193.1 R194.2 | length 166.1
  Bottom Layer w10: R193.1@2490,2110 2490,2117.01 C166.1@2552.99,2180 R194.2@2552.99,2250
NetC167_1: C167.1 R194.1 U24.5 | length 195.9
  Bottom Layer w10: U24.5@2484.88,2391.62 2552.99,2323.51 C167.1@2552.99,2320 2490,2257.01 R194.1@2490,2250
NetC168_1: C168.1 C174.1 R198.2 U26.4 | length 303.2
  Bottom Layer w10: C168.1@2641.5,2740 R198.2@2641.5,2670 C174.1@2708.5,2670 2739.21,2700.7 2739.21,2765.36 2738.5,2766.06 2738.5,2790.82 ; 2738.54,2790.86 2738.54,2820.62 U26.4@2740.32,2822.4
NetC168_2: C168.2 C173.1 R199.2 U26.5 | length 278.3
  Bottom Layer w10: C168.2@2578.5,2740 2641.5,2802.99 R199.2@2641.5,2807.01 ; R199.2@2641.5,2810 R199.2@2641.5,2807.01 ; U26.5@2720.63,2822.4 2720.63,2752.13 C173.1@2708.5,2740 R199.2@2641.5,2807.01
NetC169_1: C169.1 C172.1 R201.2 U26.6 | length 308
  Bottom Layer w10: C169.1@2578.5,3000 2580,3000 2641.5,2938.5 ; R201.2@2641.5,2900 2641.5,2938.5 ; C172.1@2708.5,3070 2720.63,3057.88 U26.6@2720.63,2997.6 2661.54,2938.5 2641.5,2938.5
NetC169_2: C169.2 C171.1 R203.2 U26.7 | length 324.6
  Bottom Layer w10: C169.2@2641.5,3000 2640,3001.5 R203.2@2640,3070 2640,3071.5 C171.1@2708.5,3140 2740.32,3108.19 U26.7@2740.32,2997.6
NetC184_1: C184.1 D54.K U29.5 | length 328.5
  Top Layer w10: U29.5@2147.5,2380.93 2153.38,2375.05 2257.12,2375.05 2287.82,2405.75 C184.1@2288.8,2405.75 2288.8,2409.21 2394.41,2409.21 2417.45,2432.25 2423.45,2432.25 2436.45,2445.25 D54.K@2436.45,2451.25
NetC186_1: C186.1 U28.4 | length 114.5
  Bottom Layer w10: C186.1@923.99,4928.87 924.98,4928.87 987.87,4865.97 1004,4865.97 U28.4@1010,4859.97
NetD1_A: D1.A R49.1 | length 138.5
  Top Layer w10: D1.A@3187.52,4350 3187.52,4367.52 v1(3230,4410)
  Bottom Layer w10: v1(3230,4410) 3260,4440 R49.1@3260,4458.5
NetD3_A: D3.A R3.1 | length 352.5
  Top Layer w10: v1(3159.77,4419.77) 3159.77,4329.28 3187.52,4301.53 D3.A@3187.52,4130
  Bottom Layer w10: v1(3159.77,4419.77) 3190,4450 R3.1@3190,4458.5
NetD6_A: D6.A D32.K | length 74.6
  Bottom Layer w10: D6.A@5008.5,1705.35 D32.K@5008.5,1780
NetD7_K: D7.K D28.A | length 74.6
  Bottom Layer w10: D28.A@4928.5,1705.35 D7.K@4928.5,1780
NetD13_K: D13.K Q28.G R43.1 | length 708.1
  Top Layer w20: v1(5261.63,981.63) Q28.G@5261.63,1013.55
  Bottom Layer w10: D13.K@5580,1300 D13.K@5600,1300
  Bottom Layer w20: v1(5261.63,981.63) 5280.32,981.63 5330,1031.3 5330,1180.47 5389.53,1240 5520,1240 D13.K@5580,1300 ; D13.K@5600,1300 R43.1@5718.5,1300
NetD16_K: D16.K D40.A | length 226.3
  Bottom Layer w20: D40.A@5640,4960 D16.K@5800,5120
NetD17_A: D17.A R92.2 | length 92.9
  Top Layer w20: D17.A@5910,5360 R92.2@6002.87,5360
NetD18_A: D18.A R52.1 R110.1 | length 255.9
  Top Layer w10: D18.A@5372.48,4710 5412.99,4710 v1(5481.5,4778.5)
  Bottom Layer w10: R110.1@5481.5,4660 R52.1@5481.5,4730 v1(5481.5,4778.5)
NetD23_K: D23.K Q18.3 R111.2 R114.2 U10.3 | length 414.8
  Top Layer w10: U10.3@1435.91,3615 1495,3615 1520,3640 R111.2@1520,3651.5 ; R111.2@1518.5,3650 R111.2@1520,3651.5 ; D23.K@1583.31,3870 1578.62,3865.32 R114.2@1578.62,3770 1578.62,3750 v1@1598.62,3730 ; v1(1595,3725.35) 1591.36,3721.72 1562.5,3721.72 1525.8,3685.01 1525.8,3657.29 R111.2@1520,3651.5
  Bottom Layer w10: v1(1595,3725.35) Q18.3@1595,3760
NetD27_A: D27.A D34.K | length 79.3
  Top Layer w10: D34.K@5909.45,2287.24 D27.A@5988.74,2287.24
NetD31_A: D31.A R75.2 | length 122
  Top Layer w10: D31.A@3187.52,3910 3187.52,3937.52 v1(3220,3970)
  Bottom Layer w10: R75.2@3171.5,3970 v1(3220,3970)
NetD33_K: D33.K D35.A | length 79.3
  Top Layer w10: D33.K@5909.45,2367.24 D35.A@5988.74,2367.24
NetD40_K: D40.K R105.2 | length 472.3
  Top Layer w20: v1(5660,5070) 5660,4980 5862.87,4777.13 R105.2@5862.87,4740
  Bottom Layer w20: D40.K@5640,5120 5640,5090 v1(5660,5070)
NetD46_K: D46.K R159.1 | length 128.9
  Top Layer w10: R159.1@2310,1878.5 2356.14,1878.5 D46.K@2414.65,1820
NetD47_K: D47.K R162.1 | length 149
  Top Layer w10: R162.1@2080,1918.5 2105.35,1893.15 D47.K@2105.35,1780
NetD49_K: D49.K Q19.3 R119.2 R123.2 U12.3 | length 409.5
  Top Layer w10: U12.3@1151.69,4330 1185.63,4330 1235.63,4380 R119.2@1235.63,4390 ; R119.2@1235.97,4390 1235.97,4425.19 R123.2@1286.5,4475.71 ; R123.2@1286.5,4470 R123.2@1295,4470 ; R123.2@1286.5,4474.99 R123.2@1286.5,4475.71 ; v1@1286.5,4499.99 R123.2@1286.5,4475.71 ; D49.K@1289.1,4555 1289.17,4555 1295,4549.17 v1(1295,4515) R123.2@1295,4477.49 ; R123.2@1295,4474.99 R123.2@1295,4477.49 ; R123.2@1286.5,4475.71 1288.28,4477.49 R123.2@1295,4477.49
  Bottom Layer w10: v1(1295,4515) 1295,4462.13 Q19.3@1297.13,4460 Q19.3@1297.13,4467.13
NetD50_K: D50.K R41.2 R45.2 U5.3 | length 319.1
  Top Layer w10: U5.3@3896.06,2282 3951.48,2282 3978.5,2309.02 R41.2@3978.5,2330 3978.5,2358.5 4041.5,2421.5 R45.2@4041.5,2430 4041.5,2494.17 4047.32,2500 D50.K@4053.31,2500
NetD57_1: D57.1 F3.1 Q13.4 Q13.6 | length 674.5
  Top Layer w20: D57.1@1157.4,5279.37 1397.76,5279.37 1436.97,5318.58 F3.1@1436.97,5350 ; v1(1220,5440) v1(1320,5440)
  Bottom Layer w20: Q13.4@1218.23,5376.3 1218.23,5432.87 v1@1228.5,5443.15 ; v1(1220,5440) v1(1320,5440) ; Q13.6@1293.03,5376.3 1315.63,5398.9 v1@1315.63,5443.15
  other v1: 1270,5440
NetD58_1: D58.1 D58.3 F4.1 Q21.4 Q21.6 | length 686.2
  Top Layer w50: F4.1@1660,5007.32 1670.47,5007.32 1675,5002.8 1675,5001.97 v1(1782.19,4894.78) v1(1822.19,4894.78) 1834.17,4894.78 1843.25,4903.86
  Bottom Layer w20: D58.3@1632.59,5022.85 1633.97,5021.48 1633.97,5001.58 1652.44,4983.1 1716.52,4983.1 ; D58.1@1707.4,5022.85 1710.98,5019.27 1710.98,4988.64 1716.52,4983.1 ; v1@1782.94,4907.05 1782.19,4897.65 1785.07,4894.78 v1(1822.19,4894.78) 1826.25,4894.78 1848.6,4917.13 1867.13,4917.13 v1(1870,4920) 1870,4961.22 Q21.4@1869.59,4961.63 ; 1787.87,4912.47 1794.79,4910.25 Q21.6@1794.79,4961.63 1738,4961.63 1716.52,4983.1
NetF5_2: F5.2 L14.1
NetFC1_2: FC1.2 GDT1.1 L13.4
  other v2: 6930,270 7030,270 7130,270 6930,370 7030,370 7130,370
NetFC4_1: FC4.1 L7.1 | length 513.7
  Top Layer w100: 7580,4210 7700,4210 ; FC4.1@7700,4111.57 7700,4210 ; FC4.1@7700,4308.43 7700,4210
  Bottom Layer w100: FC4.1@7700,4111.57 FC4.1@7700,4308.43
NetGDT1_2: GDT1.2 RV1.1 | length 545
  Internal 1 w50: RV1.1@6880.94,1012.68 7136.77,756.85 GDT1.2@7320,756.85
NetGDT2_1: GDT2.1 RV2.1 | length 360.4
  Internal 1 w100: RV2.1@7229.06,1347.32 7229.06,1692.21 GDT2.1@7240,1703.15
NetGDT3_2: GDT3.2 RV4.1 | length 550.8
  Top Layer w50: RV4.1@6912.36,3549.06 7008.31,3549.06 7114.66,3655.41 7242.26,3655.41 7316.37,3729.52 GDT3.2@7388.43,3729.52
NetGDT4_1: GDT4.1 RV5.1 | length 442.8
  Bottom Layer w50: RV5.1@6610.94,2622.36 6610.94,2605.91 6870,2346.85 GDT4.1@6870,2286.85
NetGDT5_1: GDT5.1 RV6.1 | length 462
  Top Layer w50: RV6.1@7030.94,2562.36 7090.94,2562.36 7146.46,2506.85 GDT5.1@7470,2506.85
NetJP5_2: JP5.2 L8.2 | length 512
  Bottom Layer w20: L8.2@134.57,3090 134.57,2755.43 JP5.2@260,2630
NetJP6_1: JP6.1 LA4.6 | length 677.4
  Bottom Layer w10: JP6.1@250,1074.57 360,1184.57 360,1660 374.25,1674.25 LA4.6@400.47,1674.25
NetJP6_2: JP6.2 JP6.3 | length 155.9
  Top Layer w50: JP6.2@250,1228.19 JP6.3@250,1384.09
NetJP6_4: JP6.4 LA4.7 | length 246.1
  Bottom Layer w10: JP6.4@250,1542.28 250,1590 365.75,1705.75 LA4.7@400.47,1705.75
NetJP6_5: JP6.5 L49.2 | length 761.7
  Top Layer w100: JP6.5@250,1698.19 380,1568.19 380,1260 500,1140 500,1160 L49.2@580,1160
NetJP6_6: JP6.6 LA4.8 | length 198.9
  Bottom Layer w10: JP6.6@250,1854.09 366.85,1737.24 LA4.8@400.47,1737.24
NetJP6_7: JP6.7 L50.2 | length 313
  Top Layer w50: JP6.7@250,2010 JP6.7@257.13,2002.87
  Top Layer w100: JP6.7@257.13,2002.87 L50.2@530,2002.87 L50.2@560,2002.87
NetJP7_1: JP7.1 L12.2 | length 140.6
  Bottom Layer w20: JP7.1@160,5082.36 187.64,5110 L12.2@289.13,5110
NetJP7_3: JP7.3 L15.2 | length 193.4
  Top Layer w50: JP7.3@160,5279.21 297.91,5279.21 L15.2@337.13,5240
NetJP7_4: JP7.4 L14.2 | length 182.2
  Top Layer w50: JP7.4@160,5377.64 324.76,5377.64 L14.2@337.13,5390
NetJP8_1: JP8.1 L48.2 | length 213.3
  Top Layer w100: JP8.1@200,152 368,152 400,120
NetJP8_2: JP8.2 L47.2 | length 202
  Top Layer w100: JP8.2@200,308 402,308
NetJP9_1: JP9.1 JP9.6 L33.1 | length 546.9
  Top Layer w50: JP9.6@2478.11,5316.46 2478.11,5308.18 2556.29,5230 L33.1@2787.13,5230 2676.73,5119.61 JP9.1@2635.59,5119.61
NetJP9_2: JP9.2 LA3.4 | length 182.9
  Bottom Layer w10: JP9.2@2635.59,5316.46 2635.59,5308.35 2682.44,5261.5 LA3.4@2790.94,5261.5
NetJP9_3: JP9.3 LA3.1 | length 258.6
  Bottom Layer w10: JP9.3@2556.85,5119.61 2556.85,5126.85 2598.5,5168.5 LA3.1@2790.94,5168.5
NetJP9_4: JP9.4 LA3.3 | length 269.3
  Bottom Layer w10: JP9.4@2556.85,5316.46 2641.81,5231.5 LA3.3@2790.94,5231.5
NetJP9_5: JP9.5 LA3.2 | length 346.1
  Bottom Layer w10: JP9.5@2478.11,5119.61 2558.5,5200 LA3.2@2790.94,5200
NetJP9_7: JP9.7 L27.2 | length 494.6
  Top Layer w50: L27.2@1942.87,5200 2327.25,5200 2399.37,5127.88 JP9.7@2399.37,5119.61
NetJP9_8: JP9.8 L28.1 | length 494.8
  Top Layer w50: L28.1@1942.87,5370 1942.87,5377.98 2346.12,5377.98 2399.37,5324.73 JP9.8@2399.37,5316.46
NetJP9_9: JP9.9 LA2.4 | length 120.8
  Bottom Layer w10: LA2.4@2224.49,5060 2261.02,5060 JP9.9@2320.63,5119.61
NetJP9_10: JP9.10 LA1.1 | length 425
  Bottom Layer w10: JP9.10@2320.63,5316.46 2364.17,5360 2696.1,5360 2713.34,5342.76 LA1.1@2720.47,5342.76
NetJP9_11: JP9.11 LA2.3 | length 79.9
  Bottom Layer w10: LA2.3@2192.99,5060 2192.99,5070.71 JP9.11@2241.89,5119.61
NetJP9_12: JP9.12 LA1.2 | length 507.3
  Bottom Layer w10: JP9.12@2241.89,5316.46 2305.43,5380 2714.72,5380 LA1.2@2720.47,5374.25
NetJP9_13: JP9.13 LA2.2 | length 60.3
  Bottom Layer w10: LA2.2@2161.5,5060 2161.5,5117.95 JP9.13@2163.15,5119.61
NetJP9_14: JP9.14 LA1.3 | length 594.3
  Bottom Layer w10: JP9.14@2163.15,5316.46 2243.69,5397 2711.72,5397 LA1.3@2720.47,5405.75
NetJP9_15: JP9.15 LA2.1 | length 78.5
  Bottom Layer w10: JP9.15@2084.41,5119.61 2130,5074.02 LA2.1@2130,5060
NetJP9_16: JP9.16 LA1.4 | length 686.1
  Bottom Layer w10: JP9.16@2084.41,5316.46 2205.2,5437.24 LA1.4@2720.47,5437.24
NetJP12_1: JP12.1 LA7.1 | length 122.3
  Bottom Layer w10: JP12.1@4480,5320 4480,5272.28 LA7.1@4532.76,5219.53
NetJP12_4: JP12.4 LA7.2 | length 434.4
  Bottom Layer w10: LA7.2@4564.25,5219.53 4564.25,5226.66 4540,5250.91 4540,5350 4590,5400 4680,5400 4760,5320 JP12.4@4780,5320
NetJP12_5: JP12.5 LA7.3 | length 340
  Bottom Layer w20: LA7.3@4595.75,5219.53 4602.37,5226.15 4602.37,5250.31 4620.31,5250.31 4630,5260 4820,5260 JP12.5@4880,5320
NetJP14_1: JP14.1 LA8.1 | length 670.5
  Bottom Layer w10: 448.31,4586.77 448.31,4592.68 451.18,4595.55 LA8.1@457.09,4595.55
  Bottom Layer w20: JP14.1@160,4051.57 350,4241.57 350,4488.46 448.31,4586.77
NetJP14_2: JP14.2 LA8.2 | length 604.3
  Bottom Layer w10: JP14.2@160,4150 316.54,4306.54 316.54,4493.62 449.96,4627.05 LA8.2@457.09,4627.05
NetJP14_4: JP14.4 LA8.3 | length 438.9
  Bottom Layer w10: JP14.4@160,4346.85 160,4368.58 438.34,4646.92 439.56,4646.92 451.18,4658.54 LA8.3@457.09,4658.54
NetJP14_5: JP14.5 LA8.4 | length 395.5
  Bottom Layer w10: JP14.5@160,4445.28 JP14.5@179.08,4445.28 ; 421.72,4687.91 LA8.4@454.96,4687.91
  Bottom Layer w20: JP14.5@179.08,4445.28 421.72,4687.91
NetL5_2: L5.2 R60.1 | length 93.1
  Bottom Layer w20: L5.2@4730,1115.43 R60.1@4730,1208.5
NetL8_1: L8.1 R213.1 R214.1 | length 1944.4
  Internal 2 w20: v1(310,3080) 340,3050 830,3050 860,3080 1750,3080 1790,3040 v1(1790,2990)
  Bottom Layer w20: L8.1@205.43,3090 215.43,3080 v1(310,3080) ; R214.1@1651.5,2960 1700,2960 1740,2920 ; R213.1@1740,2851.5 1740,2920 ; v1(1790,2990) 1790,2970 1740,2920
NetL9_1: L9.1 U2.9 | length 252.2
  Top Layer w50: L9.1@3170,2927.56 3250,2847.56 3250,2750 U2.9@3250,2708.5
  other v2: 3220,2670 3280,2670 3250,2710 3220,2750 3280,2750
NetL35_2: L35.2 R99.1 R215.1 | length 324.9
  Top Layer w10: R99.1@6448.98,2170 R99.1@6451.02,2167.95
  Top Layer w20: R215.1@6451.02,2020 R99.1@6451.02,2167.95
  Top Layer w30: L35.2@6430,2334.57 6452.91,2311.65 R99.1@6452.91,2170
NetL49_1: L49.1 Q4.S U19.3 | length 949.3
  Top Layer w20: Q4.S@493.55,793.55 450,750 450,647.8 467.8,630 556.97,630 U19.3@600,673.03
  Top Layer w40: Q4.S@493.55,793.55 476.45,793.55 476.45,966.45 517.13,1007.13 L49.1@540,1007.13 ; Q4.S@511.63,793.55 Q4.S@511.63,843.55 Q4.S@511.63,893.55 511.63,930 ; 511.63,930 511.63,978.75 L49.1@540,1007.13 ; 511.63,930 517.13,930 567.13,980 L49.1@540,1007.13
NetLA5_6: LA5.6 R103.2 | length 147.9
  Top Layer w10: R103.2@6081.5,2660 6127.24,2705.75 LA5.6@6210.47,2705.75
NetLA5_7: LA5.7 R104.1 | length 163.9
  Top Layer w10: R104.1@6081.5,2590 6165.75,2674.25 LA5.7@6210.47,2674.25
NetLA6_6: LA6.6 R173.1 | length 161.4
  Bottom Layer w10: R173.1@4921.5,1250 4961.5,1290 5030,1290 5044.25,1275.75 LA6.6@5044.25,1259.53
